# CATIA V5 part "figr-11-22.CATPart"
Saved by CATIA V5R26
Part number: Part1
Bounding box of the stored display mesh (mm): x -89.703 to 75.958, y -127.286 to 108.862, z -26.487 to 19.815
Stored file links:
  D:\_Deepak\CATIA\CATIA V5-6R2016_Deepak\Resources\Part files\Partfiles\c11_catia_v5_6r2016_prt\figr-11-22.CATPart
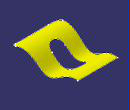
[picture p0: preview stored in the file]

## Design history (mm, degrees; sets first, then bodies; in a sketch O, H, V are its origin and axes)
Set1
  Extrude1: Element1 Sketch3, Lim1 86, Lim2 94, Direction yz-plane
  Sketch1 on xy-plane, origin (0, 0, 0), H (1, 0, 0), V (0, 1, 0)
    line L1 (64.3059, 108.8616) -> (75.9293, -106.0218)
    arc A1 centre (55.7837, -107.1115) radius 20.175 from (75.9293, -106.0218) to (55.7837, -127.2865) cw
    line L2 (55.7837, -127.2865) -> (-64.7868, -127.2865)
    arc A2 centre (-64.7868, -102.3613) radius 24.9252 from (-64.7868, -127.2865) to (-89.6873, -101.2501) cw
    line L3 (-89.6873, -101.2501) -> (-80.3115, 108.8616)
    line L4 (-80.3115, 108.8616) -> (64.3059, 108.8616)
    tangency: A1 L1, A2 L2, A2 L3, A1 L2
    horizontal: L2 H, L4 H
  Extrude2: Element1 Sketch1, Lim1 86, Lim2 94, Direction xy-plane
  Split1: ToCut Extrude1, Cutting Extrude2
  Sketch2 on xy-plane, origin (0, 0, 0), H (1, 0, 0), V (0, 1, 0)
    construction line L1 (-11.3849, 28.4134) -> (-11.3849, -36.9379)
    line L2 (12.8382, 28.4134) -> (12.8382, -36.9379)
    line L3 (-35.608, -36.9379) -> (-35.608, 28.4134)
    arc A1 centre (-11.3849, -36.9379) radius 24.2231 from (12.8382, -36.9379) to (-35.608, -36.9379) cw
    arc A2 centre (-11.3849, 28.4134) radius 24.2231 from (-35.608, 28.4134) to (12.8382, 28.4134) cw
    vertical: L1 V
    tangency: A1 L2, A2 L2, A1 L3, A2 L3
    parallelism: L1 L2
  Extrude3: Element1 Sketch2, Lim1 86, Lim2 94, Direction xy-plane
  Split2: ToCut Split1, Cutting Extrude3
  Boundary1: Boundary edge of Split2, Support Split2
Body1 (main body)
  Sketch3 on yz-plane, origin (0, 0, 0), H (0, 1, 0), V (0, 0, 1)
    spline S1 through (-130.9721, 0) (-85.5087, 19.8151) (-38.0512, 0) (0, -25.6483) (60.0541, -1.7202) (134.7951, -4.3868)
    point P1 (-130.9721, 0)
    point P2 (-38.0512, 0)
    point P3 (0, -25.6483)
    coincidence: P1 H, P2 H, P3 V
